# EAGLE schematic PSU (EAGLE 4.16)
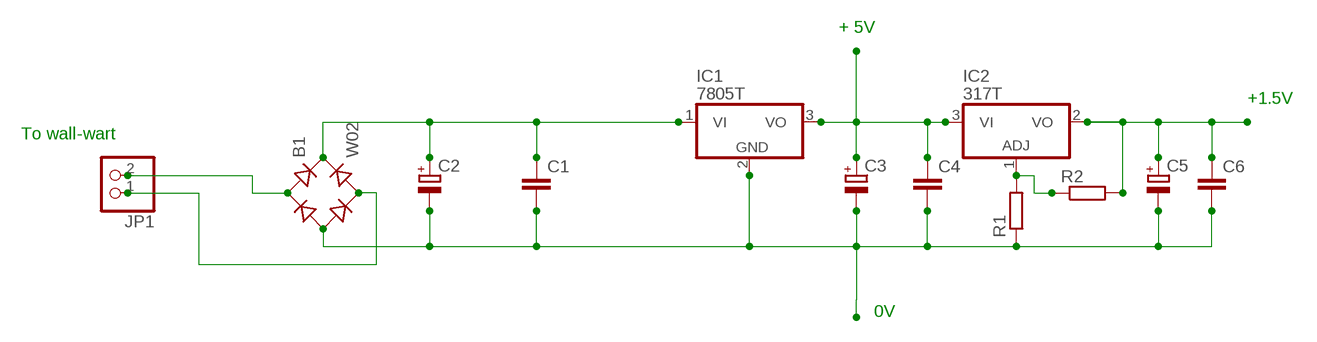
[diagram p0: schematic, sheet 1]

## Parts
B1  W02  RECTIFIER-1KAB  [1KAB]
C1  C-EU050-030X075  [C050-030X075]
C2  CPOL-EUE3.5-8  [E3,5-8]
C3  CPOL-EUE3.5-8  [E3,5-8]
C4  C-EU050-030X075  [C050-030X075]
C5  CPOL-EUE3.5-8  [E3,5-8]
C6  C-EU050-030X075  [C050-030X075]
IC1  7805T  [TO220H]
IC2  317T  [TO220H]
JP1  PINHD-1X2  [1X02]
R1  R-EU_0309/12  [0309/12]
R2  R-EU_0309/12  [0309/12]

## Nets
N$2: B1.AC1 JP1.2
N$3: B1.AC2 JP1.1
N$4: C5.+ C6.1 IC2.2(VO) R2.2
N$6: B1.+ C1.1 C2.+ IC1.1(VI)
N$8: C3.+ C4.1 IC1.3(VO) IC2.3(VI)
N$13: IC2.1(ADJ) R1.2 R2.1
N$15: B1.- C1.2 C2.- C3.- C4.2 C5.- C6.2 IC1.2(GND) R1.1

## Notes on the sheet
- + 5V
- +1.5V
- To wall-wart
- 0V

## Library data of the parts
B1 = rectifier:RECTIFIER-: Rectifier
C1 C4 C6 = rcl:C-EU: CAPACITOR, European symbol
C2 C3 C5 = rcl:CPOL-EU: POLARIZED CAPACITOR, European symbol
IC1 = linear:78*: Positive VOLTAGE REGULATOR Source: http://cache.national.com/ds/LM/LM78L05.pdf http://www.fairchildsemi.com/ds/LM/LM7805.pdf
IC2 = linear:*317: Positive VOLTAGE REGULATOR
JP1 = pinhead:PINHD-1X2: PIN HEADER
R1 R2 = rcl:R-EU_: RESISTOR, European symbol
